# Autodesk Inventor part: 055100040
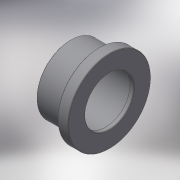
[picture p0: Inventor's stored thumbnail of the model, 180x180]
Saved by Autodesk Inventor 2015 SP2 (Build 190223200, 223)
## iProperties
Created: 2017-10
Part Number: 055100040
Material: Generic
Description: PLASSON FLANGE FLAT AD.-CEM 40
Document SubType Name: Modeling
Designer: KIM
Mass: 28.8602 g
Surface Area: 121.137 cm^2
Volume: 28.8602 cm^3
Density: 1 g/cm^3
Appearance: Default
Author: KIM
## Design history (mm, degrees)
derived "055100.ipt"
feature "Solid1::055100.ipt"
tag "TaggingFeature1"
body "Solid1"
other parameters: "d0" = 29, "d3" = 36, "d4" = 8, "d5" = 26, "d6" = 61, "d8" = 0.4, "E_1" = 61, "l_" = 26, "B_" = 8, "H_" = 29
